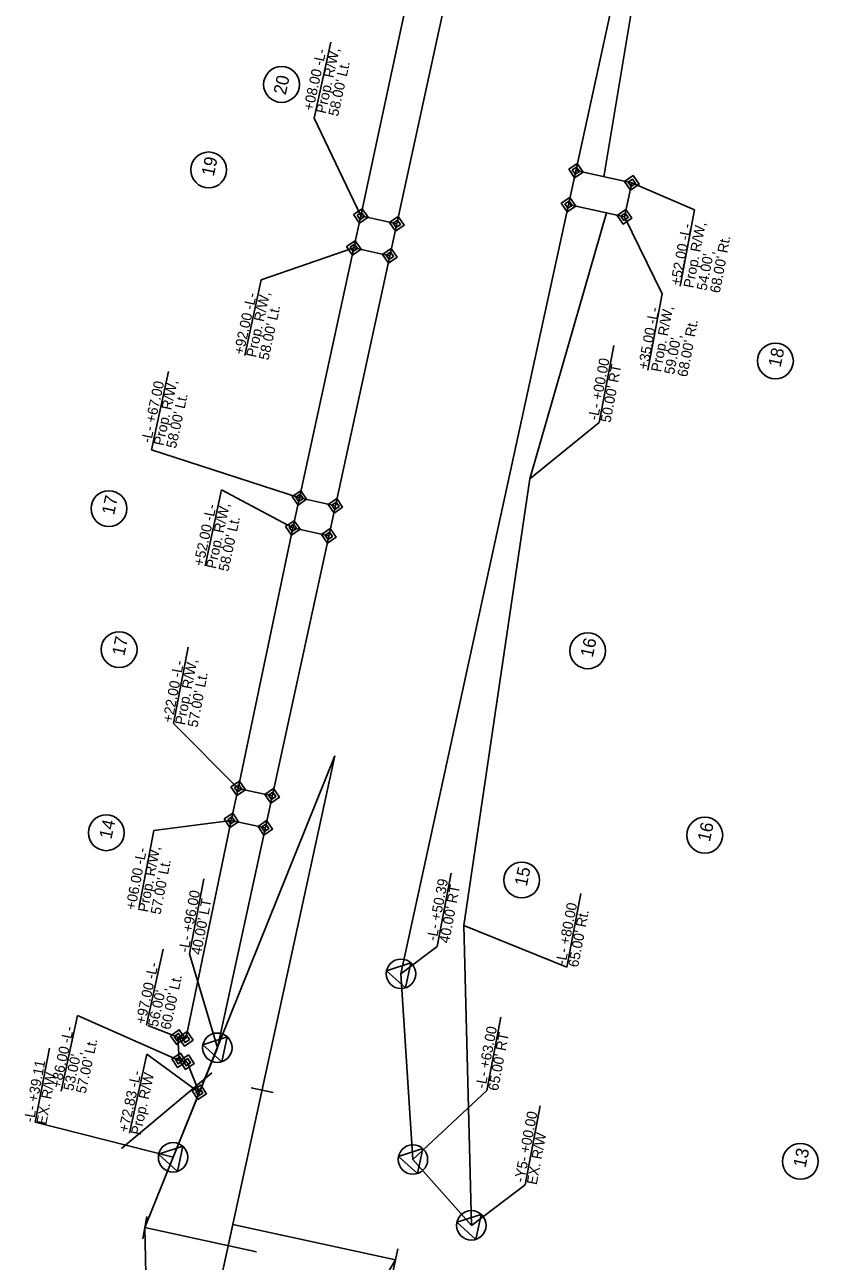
# Model space of a CAD drawing. Extents: x 1610947 to 1617684, y 899814 to 904658.
# Drawn here: x 1616310 to 1616697, y 900698 to 901302 of the extents above; entities that cross this region are included whole.
import ezdxf

# ---------------------------------------------------------------- set-up
doc = ezdxf.new("R2010")
doc.units = 0
for name, color, linetype in [('Prop Conc 1ft 6in Curb and Gutter', 7, 'Continuous'), ('Prop Conc Valley Gutter', 7, 'Continuous'), ('Prop EOT Dash', 7, 'Continuous'), ('Prop Hatching', 7, 'Continuous'), ('Prop Horizontal Alignment Curve and Spiral Data', 7, 'Continuous'), ('Prop Horizontal Alignment Direction Label', 7, 'Continuous'), ('Prop Horizontal Alignment Tick Label', 7, 'Continuous'), ('Prop Horizontal Alignment Tick Large', 7, 'Continuous'), ('Prop ROW Marker CELL', 7, 'Continuous'), ('Prop ROW RW Lines', 7, 'Continuous'), ('Prop ROW Station Offsets', 7, 'Continuous'), ('Scratch_Level_2', 7, 'Continuous'), ('Scratch_Level_3', 7, 'Continuous'), ('Scratch_Level_8', 7, 'Continuous')]:
    doc.layers.add(name, color=color, linetype=linetype)

msp = doc.modelspace()

# ---------------------------------------------------------------- linework, layer by layer
at = {"layer": 'Prop Conc 1ft 6in Curb and Gutter'}
for p, q in [((1616597.59, 901145.54), (1616590.44, 901107.89)), ((1616556.41, 901080.24), (1616590.44, 901107.89)), ((1616581.43, 900877.67), (1616574.62, 900841.81)), ((1616524.23, 900862.09), (1616574.62, 900841.81))]:
    msp.add_line(p, q, dxfattribs=at)
at = {"layer": 'Prop Conc Valley Gutter'}
msp.add_line((1616356.93, 900753.22), (1616401.11, 900790.18), dxfattribs=at)
at = {"layer": 'Prop EOT Dash'}
for points in [[(1616575.46, 901231.56), (1616579.66, 901234.42), (1616582.53, 901230.21), (1616578.32, 901227.35)], [(1616577.22, 901231.22), (1616579.33, 901232.65), (1616580.76, 901230.55), (1616578.66, 901229.12)], [(1616602.81, 901225.6), (1616607.02, 901228.46), (1616609.89, 901224.25), (1616605.68, 901221.39)], [(1616604.58, 901225.26), (1616606.69, 901226.69), (1616608.12, 901224.59), (1616606.01, 901223.16)], [(1616571.84, 901214.95), (1616576.04, 901217.81), (1616578.91, 901213.6), (1616574.7, 901210.74)], [(1616573.6, 901214.61), (1616575.71, 901216.04), (1616577.14, 901213.94), (1616575.04, 901212.51)], [(1616470.34, 901209.43), (1616474.54, 901212.29), (1616477.41, 901208.08), (1616473.2, 901205.22)], [(1616472.1, 901209.09), (1616474.21, 901210.52), (1616475.64, 901208.42), (1616473.54, 901206.99)], [(1616599.19, 901208.99), (1616603.4, 901211.85), (1616606.27, 901207.64), (1616602.06, 901204.78)], [(1616600.96, 901208.65), (1616603.07, 901210.08), (1616604.5, 901207.98), (1616602.4, 901206.55)], [(1616487.92, 901205.59), (1616492.13, 901208.46), (1616495, 901204.25), (1616490.79, 901201.39)], [(1616489.69, 901205.26), (1616491.79, 901206.69), (1616493.23, 901204.59), (1616491.12, 901203.15)], [(1616466.93, 901193.79), (1616471.14, 901196.66), (1616474, 901192.45), (1616469.79, 901189.58)], [(1616468.7, 901193.46), (1616470.8, 901194.89), (1616472.23, 901192.79), (1616470.13, 901191.35)], [(1616484.52, 901189.96), (1616488.72, 901192.83), (1616491.59, 901188.62), (1616487.38, 901185.75)], [(1616486.28, 901189.63), (1616488.39, 901191.06), (1616489.82, 901188.95), (1616487.72, 901187.52)], [(1616440.32, 901071.66), (1616444.53, 901074.52), (1616447.39, 901070.31), (1616443.19, 901067.45)], [(1616442.09, 901071.32), (1616444.19, 901072.75), (1616445.63, 901070.65), (1616443.52, 901069.22)], [(1616457.91, 901067.83), (1616462.12, 901070.69), (1616464.98, 901066.48), (1616460.77, 901063.62)], [(1616459.68, 901067.49), (1616461.78, 901068.92), (1616463.21, 901066.82), (1616461.11, 901065.39)], [(1616437.13, 901057), (1616441.34, 901059.87), (1616444.2, 901055.66), (1616439.99, 901052.79)], [(1616438.9, 901056.67), (1616441, 901058.1), (1616442.43, 901055.99), (1616440.33, 901054.56)], [(1616454.72, 901053.17), (1616458.92, 901056.03), (1616461.79, 901051.83), (1616457.58, 901048.96)], [(1616456.48, 901052.83), (1616458.59, 901054.27), (1616460.02, 901052.16), (1616457.92, 901050.73)], [(1616410.4, 900929.77), (1616414.61, 900932.64), (1616417.47, 900928.43), (1616413.27, 900925.57)], [(1616412.17, 900929.44), (1616414.27, 900930.87), (1616415.7, 900928.77), (1616413.6, 900927.33)], [(1616427.04, 900926.15), (1616431.25, 900929.01), (1616434.12, 900924.81), (1616429.91, 900921.94)], [(1616428.81, 900925.81), (1616430.92, 900927.25), (1616432.35, 900925.14), (1616430.24, 900923.71)], [(1616407.03, 900914.13), (1616411.24, 900917), (1616414.1, 900912.79), (1616409.89, 900909.93)], [(1616408.8, 900913.8), (1616410.9, 900915.23), (1616412.33, 900913.13), (1616410.23, 900911.69)], [(1616423.64, 900910.52), (1616427.85, 900913.38), (1616430.71, 900909.17), (1616426.5, 900906.31)], [(1616425.41, 900910.18), (1616427.51, 900911.61), (1616428.94, 900909.51), (1616426.84, 900908.08)], [(1616380.89, 900808.27), (1616385.1, 900811.14), (1616387.97, 900806.93), (1616383.76, 900804.06)], [(1616382.66, 900807.94), (1616384.77, 900809.37), (1616386.2, 900807.26), (1616384.09, 900805.83)], [(1616384.8, 900807.42), (1616389.01, 900810.28), (1616391.87, 900806.08), (1616387.67, 900803.21)], [(1616386.57, 900807.08), (1616388.67, 900808.52), (1616390.11, 900806.41), (1616388, 900804.98)], [(1616381.48, 900796.88), (1616385.69, 900799.75), (1616388.56, 900795.54), (1616384.35, 900792.68)], [(1616383.25, 900796.55), (1616385.36, 900797.98), (1616386.79, 900795.88), (1616384.68, 900794.44)], [(1616385.39, 900796.03), (1616389.6, 900798.9), (1616392.46, 900794.69), (1616388.26, 900791.82)], [(1616387.16, 900795.7), (1616389.26, 900797.13), (1616390.7, 900795.03), (1616388.59, 900793.59)], [(1616391.41, 900781.25), (1616395.61, 900784.11), (1616398.48, 900779.91), (1616394.27, 900777.04)], [(1616393.17, 900780.91), (1616395.28, 900782.35), (1616396.71, 900780.24), (1616394.61, 900778.81)]]:
    msp.add_lwpolyline(points, close=True, dxfattribs=at)
at = {"layer": 'Prop Hatching'}
for centre in [(1616435.12, 901272.99), (1616399.51, 901231.25), (1616676.51, 901137.91), (1616350.77, 901065.76), (1616355.76, 900996.9), (1616584.76, 900996.29), (1616349.49, 900907.4), (1616641.98, 900906.23), (1616552.49, 900884.31), (1616688.7, 900746.87)]:
    msp.add_circle(centre, 8.75, dxfattribs=at)
at = {"layer": 'Prop Horizontal Alignment Curve and Spiral Data'}
for p, q in [((1616459.23, 901293.63), (1616451.14, 901256.59)), ((1616451.14, 901256.59), (1616473.87, 901208.75)), ((1616425.21, 901177.59), (1616417.12, 901140.54)), ((1616379.86, 901132.84), (1616371.49, 901094.51)), ((1616371.49, 901094.51), (1616443.86, 901070.99)), ((1616405.85, 901074.87), (1616397.85, 901037.81)), ((1616405.85, 901074.87), (1616440.66, 901056.33)), ((1616389.45, 900998.07), (1616382.38, 900960.82)), ((1616372.64, 900908.52), (1616365.56, 900871.27)), ((1616372.64, 900908.52), (1616410.56, 900913.46))]:
    msp.add_line(p, q, dxfattribs=at)
for points in [[(1616425.21, 901177.59), (1616470.47, 901193.12)], [(1616382.38, 900960.82), (1616413.97, 900929.1)]]:
    msp.add_lwpolyline(points, dxfattribs=at)
at = {"layer": 'Prop Horizontal Alignment Direction Label'}
for p, q in [((1616473.87, 901208.75), (1616544.78, 901540.4)), ((1616443.86, 901070.99), (1616470.47, 901193.12)), ((1616413.97, 900929.1), (1616440.66, 901056.33)), ((1616388.34, 900806.75), (1616410.56, 900913.46)), ((1616388.34, 900806.75), (1616384.43, 900807.6)), ((1616385.02, 900796.21), (1616384.43, 900807.6)), ((1616388.93, 900795.36), (1616385.02, 900796.21)), ((1616394.94, 900780.58), (1616388.93, 900795.36))]:
    msp.add_line(p, q, dxfattribs=at)
at = {"layer": 'Prop Horizontal Alignment Tick Label'}
for p, q in [((1616377.2, 900850.5), (1616369.11, 900813.46)), ((1616335.47, 900818.15), (1616327.38, 900781.1)), ((1616335.47, 900818.15), (1616385.02, 900796.21)), ((1616369.22, 900799.16), (1616360.79, 900760.58))]:
    msp.add_line(p, q, dxfattribs=at)
for points in [[(1616369.72, 900813.32), (1616384.43, 900807.6)], [(1616369.22, 900799.16), (1616394.94, 900780.58)]]:
    msp.add_lwpolyline(points, dxfattribs=at)
at = {"layer": 'Prop Horizontal Alignment Tick Large'}
for p, q in [((1616578.99, 901230.89), (1616606.35, 901224.93)), ((1616602.73, 901208.31), (1616606.35, 901224.93)), ((1616575.37, 901214.27), (1616602.73, 901208.31)), ((1616470.47, 901193.12), (1616473.87, 901208.75)), ((1616491.46, 901204.92), (1616473.87, 901208.75)), ((1616488.05, 901189.29), (1616470.47, 901193.12)), ((1616440.66, 901056.33), (1616443.86, 901070.99)), ((1616461.45, 901067.15), (1616443.86, 901070.99)), ((1616458.25, 901052.5), (1616440.66, 901056.33)), ((1616410.56, 900913.46), (1616413.97, 900929.1)), ((1616430.58, 900925.48), (1616413.97, 900929.1)), ((1616427.17, 900909.84), (1616410.56, 900913.46))]:
    msp.add_line(p, q, dxfattribs=at)
at = {"layer": 'Prop ROW Marker CELL'}
for p, q in [((1616578.99, 901230.89), (1616578.99, 901230.89)), ((1616606.35, 901224.93), (1616606.35, 901224.93)), ((1616575.37, 901214.27), (1616575.37, 901214.27)), ((1616473.87, 901208.75), (1616473.87, 901208.75)), ((1616491.46, 901204.92), (1616491.46, 901204.92)), ((1616602.73, 901208.31), (1616602.73, 901208.31)), ((1616470.47, 901193.12), (1616470.47, 901193.12)), ((1616488.05, 901189.29), (1616488.05, 901189.29)), ((1616443.86, 901070.99), (1616443.86, 901070.99)), ((1616461.45, 901067.15), (1616461.45, 901067.15)), ((1616440.66, 901056.33), (1616440.66, 901056.33)), ((1616458.25, 901052.5), (1616458.25, 901052.5)), ((1616413.94, 900929.1), (1616413.94, 900929.1)), ((1616430.58, 900925.48), (1616430.58, 900925.48)), ((1616410.56, 900913.46), (1616410.56, 900913.46)), ((1616427.17, 900909.84), (1616427.17, 900909.84)), ((1616493.5, 900838.48), (1616493.5, 900838.48)), ((1616384.43, 900807.6), (1616384.43, 900807.6)), ((1616388.34, 900806.75), (1616388.34, 900806.75)), ((1616403.76, 900802.37), (1616403.76, 900802.37)), ((1616385.02, 900796.21), (1616385.02, 900796.21)), ((1616388.93, 900795.36), (1616388.93, 900795.36)), ((1616394.94, 900780.58), (1616394.94, 900780.58)), ((1616382.11, 900748.85), (1616382.11, 900748.85)), ((1616499.33, 900747.77), (1616499.33, 900747.77)), ((1616527.9, 900715.59), (1616527.9, 900715.59))]:
    msp.add_line(p, q, dxfattribs=at)
for points in [[(1616495.73, 900831.62), (1616486.46, 900839.98), (1616498.32, 900843.85)], [(1616405.98, 900795.5), (1616396.72, 900803.86), (1616408.58, 900807.73)], [(1616384.33, 900741.99), (1616375.06, 900750.35), (1616386.92, 900754.22)], [(1616501.55, 900740.91), (1616492.29, 900749.27), (1616504.15, 900753.14)], [(1616530.13, 900708.73), (1616520.86, 900717.08), (1616532.72, 900720.95)]]:
    msp.add_lwpolyline(points, close=True, dxfattribs=at)
for centre in [(1616493.5, 900838.48), (1616403.76, 900802.37), (1616382.11, 900748.85), (1616499.33, 900747.77), (1616527.9, 900715.59)]:
    msp.add_circle(centre, 7.2, dxfattribs=at)
at = {"layer": 'Prop ROW RW Lines'}
for p, q in [((1616403.76, 900802.37), (1616554.56, 901494.57)), ((1616493.5, 900838.48), (1616632.73, 901477.54)), ((1616499.33, 900747.77), (1616493.5, 900838.48)), ((1616382.11, 900748.85), (1616403.76, 900802.37)), ((1616527.9, 900715.59), (1616499.33, 900747.77))]:
    msp.add_line(p, q, dxfattribs=at)
at = {"layer": 'Prop ROW Station Offsets'}
for p, q in [((1616517.95, 900887.62), (1616511.14, 900851.76)), ((1616390.16, 900848.28), (1616403.76, 900802.37)), ((1616493.5, 900838.48), (1616511.14, 900851.76)), ((1616542.27, 900817.29), (1616535.46, 900781.43)), ((1616499.33, 900747.77), (1616535.46, 900781.43)), ((1616561.46, 900774.02), (1616554.14, 900735.44)), ((1616314.76, 900765.94), (1616382.11, 900748.85)), ((1616527.9, 900715.59), (1616554.14, 900735.44))]:
    msp.add_line(p, q, dxfattribs=at)
for points in [[(1616397.13, 900884.97), (1616390.16, 900848.28)], [(1616321.64, 900802.19), (1616314.76, 900765.94)]]:
    msp.add_lwpolyline(points, dxfattribs=at)
at = {"layer": 'Scratch_Level_2'}
for p, q in [((1616368.26, 900714.52), (1616461.19, 900945.02)), ((1616461.19, 900945.02), (1616409.04, 900705.63)), ((1616420.23, 900782.86), (1616430.98, 900780.52)), ((1616367.28, 900709.09), (1616369.24, 900719.94)), ((1616368.26, 900714.52), (1616422.96, 900702.6)), ((1616375.73, 900418.83), (1616368.26, 900714.52)), ((1616490.82, 900698.78), (1616411.32, 900716.1)), ((1616491.95, 900704.16), (1616489.69, 900693.39))]:
    msp.add_line(p, q, dxfattribs=at)
msp.add_lwpolyline([(1616411.32, 900716.1), (1616359.17, 900476.71), (1616490.82, 900698.78)], dxfattribs=at)
at = {"layer": 'Scratch_Level_3'}
for p, q in [((1616592.67, 901227.91), (1616619.55, 901388.87)), ((1616556.41, 901080.24), (1616593.94, 901210.23)), ((1616524.23, 900862.09), (1616556.41, 901080.24)), ((1616527.9, 900715.59), (1616524.23, 900862.09))]:
    msp.add_line(p, q, dxfattribs=at)
at = {"layer": 'Scratch_Level_8'}
for p, q in [((1616637.03, 901211.73), (1616629.96, 901174.48)), ((1616621.14, 901170.73), (1616614.07, 901133.47))]:
    msp.add_line(p, q, dxfattribs=at)
for points in [[(1616637.03, 901211.73), (1616606.35, 901224.93)], [(1616621.14, 901170.73), (1616602.73, 901208.31)]]:
    msp.add_lwpolyline(points, dxfattribs=at)

# ---------------------------------------------------------------- texts
at = {"layer": 'Prop Conc 1ft 6in Curb and Gutter'}
for s, p in [('-L- +00.00', (1616589.75, 901108.66)), ("50.00' RT", (1616595.89, 901107.5)), ('-L- +80.00', (1616573.92, 900842.59)), ("65.00' Rt.", (1616580.06, 900841.42))]:
    msp.add_text(s, height=5, rotation=79.24937, dxfattribs=at).set_placement(p)
at = {"layer": 'Prop Hatching'}
for s, p in [('20', (1616437.15, 901267.61)), ('19', (1616401.96, 901227.84)), ('18', (1616678.96, 901134.5)), ('17', (1616353.23, 901062.36)), ('17', (1616358.22, 900993.49)), ('16', (1616587.18, 900992.74)), ('14', (1616351.95, 900904)), ('16', (1616644.41, 900902.68)), ('15', (1616554.95, 900880.91)), ('13', (1616691.16, 900743.47))]:
    msp.add_text(s, height=6.25, rotation=77.71667, dxfattribs=at).set_placement(p)
at = {"layer": 'Prop Horizontal Alignment Curve and Spiral Data'}
for s, rotation, p in [('+08.00 -L-', 77.68623, (1616450.54, 901259.81)), ('Prop. R/W,', 77.68623, (1616456.64, 901258.47)), ("58.00' Lt.", 77.68623, (1616462.75, 901257.14)), ('+92.00 -L-', 77.68623, (1616416.51, 901140.68)), ('Prop. R/W,', 77.68623, (1616422.62, 901139.34)), ("58.00' Lt.", 77.68623, (1616428.73, 901138.01)), ('-L- +67.00', 77.68623, (1616371.28, 901097.54)), ('Prop. R/W,', 77.68623, (1616377.39, 901096.2)), ("58.00' Lt.", 77.68623, (1616383.49, 901094.87)), ('+52.00 -L-', 77.81366, (1616396.89, 901037.4)), ('Prop. R/W,', 77.81366, (1616403, 901036.08)), ("58.00' Lt.", 77.81366, (1616409.11, 901034.76)), ('+22.00 -L-', 79.24937, (1616381.76, 900960.94)), ('Prop. R/W,', 79.24937, (1616387.9, 900959.77)), ("57.00' Lt.", 79.24937, (1616394.04, 900958.61)), ('+06.00 -L-', 79.24937, (1616363.66, 900869.49)), ('Prop. R/W,', 79.24937, (1616369.8, 900868.32)), ("57.00' Lt.", 79.24937, (1616375.94, 900867.16))]:
    msp.add_text(s, height=5, rotation=rotation, dxfattribs=at).set_placement(p)
at = {"layer": 'Prop Horizontal Alignment Tick Label'}
for s, p in [('+97.00 -L-', (1616368.5, 900813.59)), ("60.00' Lt.", (1616380.72, 900810.92)), ("56.00',", (1616374.61, 900812.26)), ('+86.00 -L-', (1616327.15, 900782.32)), ("57.00' Lt.", (1616339.37, 900779.66)), ("53.00',", (1616333.26, 900780.99)), ('+72.83 -L-', (1616360.18, 900760.71)), ('Prop. R/W', (1616366.29, 900759.38))]:
    msp.add_text(s, height=5, rotation=77.68623, dxfattribs=at).set_placement(p)
at = {"layer": 'Prop ROW Station Offsets'}
for s, p in [('-L- +50.39', (1616510.86, 900854.3)), ('-L- +96.00', (1616389.64, 900848.66)), ("40.00' RT", (1616517, 900853.13)), ("40.00' LT", (1616395.78, 900847.5)), ('-L- +63.00', (1616534.76, 900782.2)), ("65.00' RT", (1616540.9, 900781.04)), ('-L- +39.11', (1616314, 900765.7)), ('EX. R/W', (1616320.14, 900764.53)), ('-Y5- +00.00', (1616553.67, 900736.31)), ('EX. R/W', (1616559.81, 900735.15))]:
    msp.add_text(s, height=5, rotation=79.24937, dxfattribs=at).set_placement(p)
at = {"layer": 'Scratch_Level_8'}
for s, p in [('+52.00 -L-', (1616629.96, 901174.48)), ('Prop. R/W,', (1616636.4, 901173.26)), ("68.00' Rt.", (1616649.28, 901170.81)), ("54.00',", (1616642.84, 901172.03)), ('+35.00 -L-', (1616614.07, 901133.47)), ('Prop. R/W,', (1616620.51, 901132.25)), ("68.00' Rt.", (1616633.39, 901129.81)), ("59.00',", (1616626.95, 901131.03))]:
    msp.add_text(s, height=5, rotation=79.24937, dxfattribs=at).set_placement(p)

doc.saveas('drawing.dxf')
